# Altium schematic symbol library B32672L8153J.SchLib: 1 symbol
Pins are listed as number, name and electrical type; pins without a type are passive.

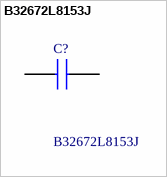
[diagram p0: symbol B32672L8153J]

## B32672L8153J
designator C?
Film Capacitors Film Cap 15NF 5% 700VAC MKP BOXED; Manufacturer_Name: TDK; Geometry.Height: 14.5mm
footprint B32672L8153J
pins: 1, 2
